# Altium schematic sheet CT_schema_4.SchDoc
size 283 x 147 mm
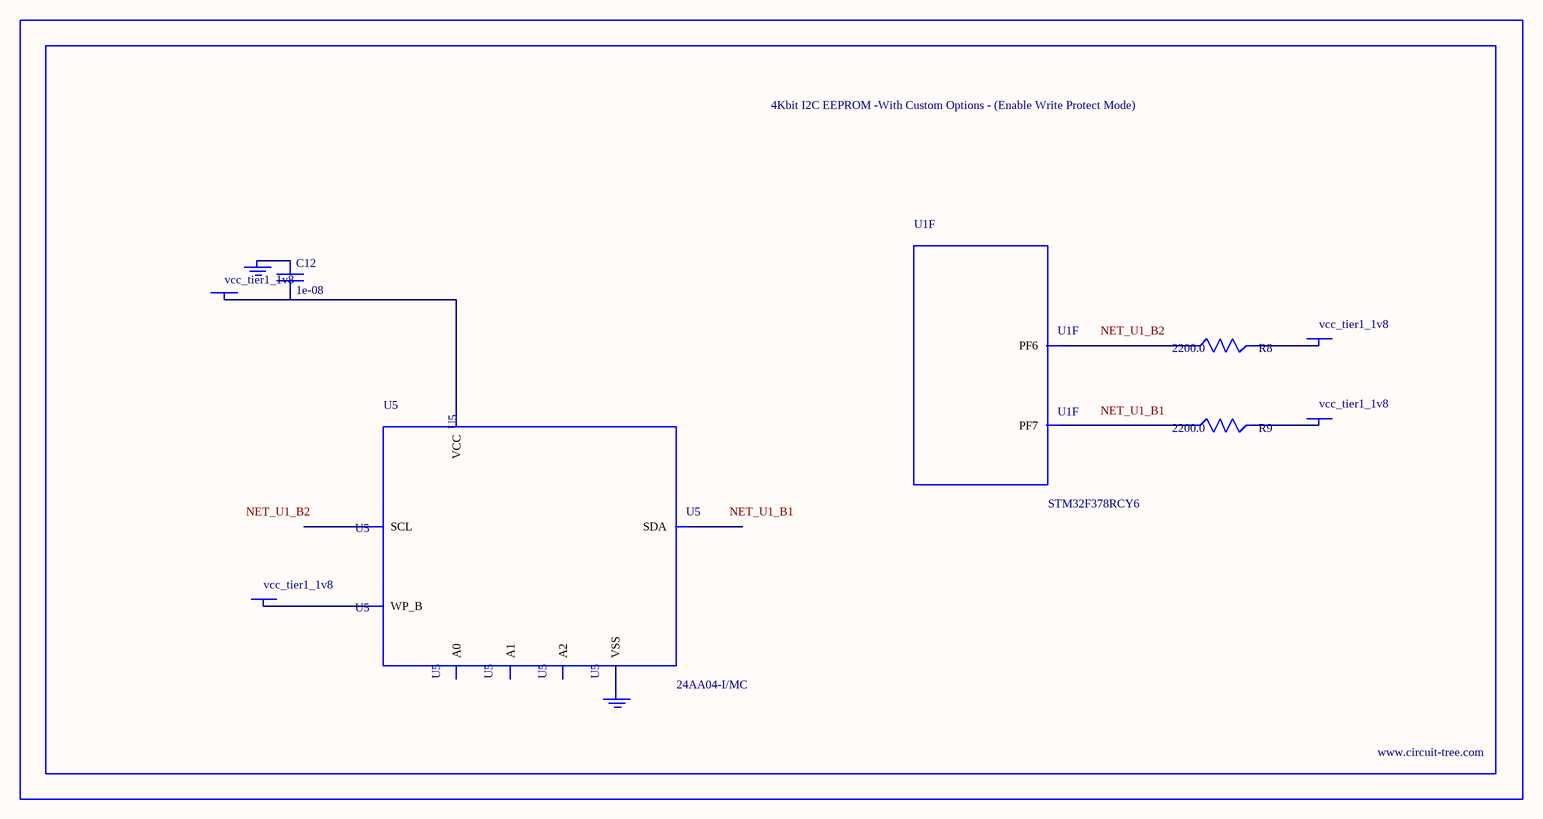
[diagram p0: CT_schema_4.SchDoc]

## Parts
BORDER3  (no value)
C12  1e-08  [C0402]
GND_INSTANCE_3_0  (no value)
GND_INSTANCE_3_1  (no value)
POWER_INSTANCE_3_0  vcc_tier1_1v8
POWER_INSTANCE_3_1  vcc_tier1_1v8
POWER_INSTANCE_3_2  vcc_tier1_1v8
POWER_INSTANCE_3_3  vcc_tier1_1v8
R8  2200.0  [R0603]
R9  2200.0  [R0603]
U1  STM32F378RCY6  [WLCSP66_8X8]  (part F of 6)
U5  24AA04-I/MC  [TDFN-8/6MM]

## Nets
NetC12_1: C12.1 GND_INSTANCE_3_0.0(GND)
NetC12_2: C12.2 POWER_INSTANCE_3_1.0(PWR) U5.8(VCC)
NetGND_INSTANCE_3_1_0: GND_INSTANCE_3_1.0(GND) U5.4(VSS)
NetPOWER_INSTANCE_3_0_0: POWER_INSTANCE_3_0.0(PWR) U5.7(WP_B)
NetPOWER_INSTANCE_3_2_0: POWER_INSTANCE_3_2.0(PWR) R8.2
NetPOWER_INSTANCE_3_3_0: POWER_INSTANCE_3_3.0(PWR) R9.2
NetR8_1: R8.1 U1.B2(PF6)
NetR9_1: R9.1 U1.B1(PF7)

Not connected (* = marked no-connect by the designer): U5 1(A0) 2(A1) 3(A2) 5(SDA) 6(SCL)

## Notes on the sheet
- Labels drawn without touching a wire or pin: NET_U1_B1, NET_U1_B2

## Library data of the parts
BORDER3 = BORDER_PAGE3
C12 = C0402C103K3RAC
GND_INSTANCE_3_0 GND_INSTANCE_3_1 = GND
POWER_INSTANCE_3_0-POWER_INSTANCE_3_3 = PWR
R8 R9 = RC0603JR-072K2L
